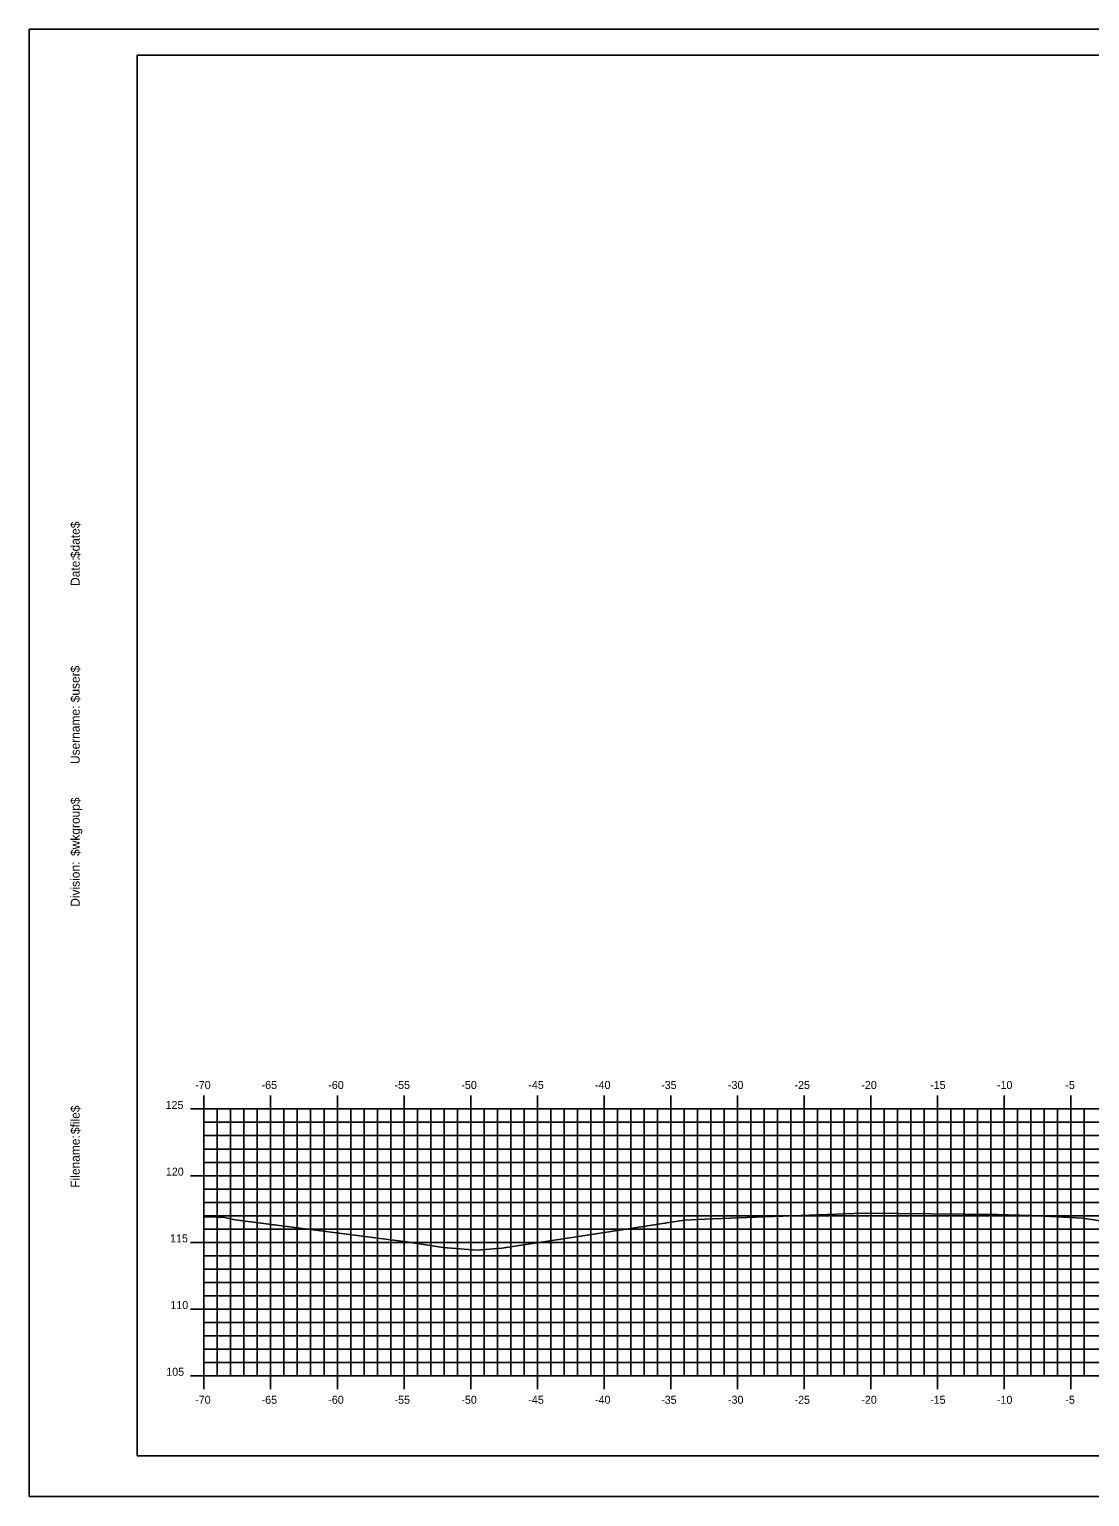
# Model space of a CAD drawing. Extents: x 853956 to 854128, y 365624 to 365734.
# Drawn here: x 853956 to 854035.5, y 365624 to 365734 of the extents above; entities that cross this region are included whole.
import ezdxf

# ---------------------------------------------------------------- set-up
doc = ezdxf.new("R2010")
doc.units = 0
for name, color, linetype in [('BORDER', 7, 'Continuous'), ('H_V ANNOTATION', 7, 'Continuous'), ('M_Roadway_Centerline', 7, 'Continuous'), ('MAJOR', 7, 'Continuous'), ('MINOR', 7, 'Continuous'), ('PLOT BOUNDARY', 7, 'Continuous'), ('S_Roadway_Centerline', 7, 'Continuous')]:
    doc.layers.add(name, color=color, linetype=linetype)

msp = doc.modelspace()

# ---------------------------------------------------------------- linework, layer by layer
at = {"layer": 'BORDER'}
msp.add_lwpolyline([(853964.09, 365627.03), (854124.09, 365627.03), (854124.09, 365732.03), (853964.09, 365732.03)], close=True, dxfattribs=at)
at = {"layer": 'MAJOR'}
for p, q in [((853969.09, 365654.03), (853969.09, 365653.03)), ((853974.09, 365654.03), (853974.09, 365653.03)), ((853979.09, 365654.03), (853979.09, 365653.03)), ((853984.09, 365654.03), (853984.09, 365653.03)), ((853989.09, 365654.03), (853989.09, 365653.03)), ((853994.09, 365654.03), (853994.09, 365653.03)), ((853999.09, 365654.03), (853999.09, 365653.03)), ((854004.09, 365654.03), (854004.09, 365653.03)), ((854009.09, 365654.03), (854009.09, 365653.03)), ((854014.09, 365654.03), (854014.09, 365653.03)), ((854019.09, 365654.03), (854019.09, 365653.03)), ((854024.09, 365654.03), (854024.09, 365653.03)), ((854029.09, 365654.03), (854029.09, 365653.03)), ((854034.09, 365654.03), (854034.09, 365653.03)), ((853968.09, 365653.03), (853969.09, 365653.03)), ((853969.09, 365653.03), (854109.09, 365653.03)), ((853969.09, 365633.03), (853969.09, 365653.03)), ((853969.09, 365633.03), (853969.09, 365653.03)), ((853969.09, 365653.03), (854109.09, 365653.03)), ((853974.09, 365633.03), (853974.09, 365653.03)), ((853979.09, 365633.03), (853979.09, 365653.03)), ((853984.09, 365633.03), (853984.09, 365653.03)), ((853989.09, 365633.03), (853989.09, 365653.03)), ((853994.09, 365633.03), (853994.09, 365653.03)), ((853999.09, 365633.03), (853999.09, 365653.03)), ((854004.09, 365633.03), (854004.09, 365653.03)), ((854009.09, 365633.03), (854009.09, 365653.03)), ((854014.09, 365633.03), (854014.09, 365653.03)), ((854019.09, 365633.03), (854019.09, 365653.03)), ((854024.09, 365633.03), (854024.09, 365653.03)), ((854029.09, 365633.03), (854029.09, 365653.03)), ((854034.09, 365633.03), (854034.09, 365653.03)), ((853968.09, 365648.03), (853969.09, 365648.03)), ((853969.09, 365648.03), (854109.09, 365648.03)), ((853968.09, 365643.03), (853969.09, 365643.03)), ((853969.09, 365643.03), (854109.09, 365643.03)), ((853968.09, 365638.03), (853969.09, 365638.03)), ((853969.09, 365638.03), (854109.09, 365638.03)), ((853968.09, 365633.03), (853969.09, 365633.03)), ((853969.09, 365633.03), (854109.09, 365633.03)), ((853969.09, 365633.03), (854109.09, 365633.03)), ((853969.09, 365632.02), (853969.09, 365633.03)), ((853974.09, 365632.02), (853974.09, 365633.03)), ((853979.09, 365632.02), (853979.09, 365633.03)), ((853984.09, 365632.02), (853984.09, 365633.03)), ((853989.09, 365632.02), (853989.09, 365633.03)), ((853994.09, 365632.02), (853994.09, 365633.03)), ((853999.09, 365632.02), (853999.09, 365633.03)), ((854004.09, 365632.02), (854004.09, 365633.03)), ((854009.09, 365632.02), (854009.09, 365633.03)), ((854014.09, 365632.02), (854014.09, 365633.03)), ((854019.09, 365632.02), (854019.09, 365633.03)), ((854024.09, 365632.02), (854024.09, 365633.03)), ((854029.09, 365632.02), (854029.09, 365633.03)), ((854034.09, 365632.02), (854034.09, 365633.03))]:
    msp.add_line(p, q, dxfattribs=at)
at = {"layer": 'MINOR'}
for p, q in [((853970.09, 365633.03), (853970.09, 365653.03)), ((853971.09, 365633.03), (853971.09, 365653.03)), ((853972.09, 365633.03), (853972.09, 365653.03)), ((853973.09, 365633.03), (853973.09, 365653.03)), ((853975.09, 365633.03), (853975.09, 365653.03)), ((853976.09, 365633.03), (853976.09, 365653.03)), ((853977.09, 365633.03), (853977.09, 365653.03)), ((853978.09, 365633.03), (853978.09, 365653.03)), ((853980.09, 365633.03), (853980.09, 365653.03)), ((853981.09, 365633.03), (853981.09, 365653.03)), ((853982.09, 365633.03), (853982.09, 365653.03)), ((853983.09, 365633.03), (853983.09, 365653.03)), ((853985.09, 365633.03), (853985.09, 365653.03)), ((853986.09, 365633.03), (853986.09, 365653.03)), ((853987.09, 365633.03), (853987.09, 365653.03)), ((853988.09, 365633.03), (853988.09, 365653.03)), ((853990.09, 365633.03), (853990.09, 365653.03)), ((853991.09, 365633.03), (853991.09, 365653.03)), ((853992.09, 365633.03), (853992.09, 365653.03)), ((853993.09, 365633.03), (853993.09, 365653.03)), ((853995.09, 365633.03), (853995.09, 365653.03)), ((853996.09, 365633.03), (853996.09, 365653.03)), ((853997.09, 365633.03), (853997.09, 365653.03)), ((853998.09, 365633.03), (853998.09, 365653.03)), ((854000.09, 365633.03), (854000.09, 365653.03)), ((854001.09, 365633.03), (854001.09, 365653.03)), ((854002.09, 365633.03), (854002.09, 365653.03)), ((854003.09, 365633.03), (854003.09, 365653.03)), ((854005.09, 365633.03), (854005.09, 365653.03)), ((854006.09, 365633.03), (854006.09, 365653.03)), ((854007.09, 365633.03), (854007.09, 365653.03)), ((854008.09, 365633.03), (854008.09, 365653.03)), ((854010.09, 365633.03), (854010.09, 365653.03)), ((854011.09, 365633.03), (854011.09, 365653.03)), ((854012.09, 365633.03), (854012.09, 365653.03)), ((854013.09, 365633.03), (854013.09, 365653.03)), ((854015.09, 365633.03), (854015.09, 365653.03)), ((854016.09, 365633.03), (854016.09, 365653.03)), ((854017.09, 365633.03), (854017.09, 365653.03)), ((854018.09, 365633.03), (854018.09, 365653.03)), ((854020.09, 365633.03), (854020.09, 365653.03)), ((854021.09, 365633.03), (854021.09, 365653.03)), ((854022.09, 365633.03), (854022.09, 365653.03)), ((854023.09, 365633.03), (854023.09, 365653.03)), ((854025.09, 365633.03), (854025.09, 365653.03)), ((854026.09, 365633.03), (854026.09, 365653.03)), ((854027.09, 365633.03), (854027.09, 365653.03)), ((854028.09, 365633.03), (854028.09, 365653.03)), ((854030.09, 365633.03), (854030.09, 365653.03)), ((854031.09, 365633.03), (854031.09, 365653.03)), ((854032.09, 365633.03), (854032.09, 365653.03)), ((854033.09, 365633.03), (854033.09, 365653.03)), ((854035.09, 365633.03), (854035.09, 365653.03)), ((853969.09, 365652.03), (854109.09, 365652.03)), ((853969.09, 365652.03), (853970.09, 365652.03)), ((853969.09, 365651.03), (854109.09, 365651.03)), ((853969.09, 365651.03), (853970.09, 365651.03)), ((853969.09, 365650.03), (854109.09, 365650.03)), ((853969.09, 365650.03), (853970.09, 365650.03)), ((853969.09, 365649.03), (854109.09, 365649.03)), ((853969.09, 365649.03), (853970.09, 365649.03)), ((853969.09, 365647.03), (854109.09, 365647.03)), ((853969.09, 365647.03), (853970.09, 365647.03)), ((853969.09, 365646.03), (854109.09, 365646.03)), ((853969.09, 365646.03), (853970.09, 365646.03)), ((853969.09, 365645.03), (854109.09, 365645.03)), ((853969.09, 365645.03), (853970.09, 365645.03)), ((853969.09, 365644.03), (854109.09, 365644.03)), ((853969.09, 365644.03), (853970.09, 365644.03)), ((853969.09, 365642.03), (854109.09, 365642.03)), ((853969.09, 365642.03), (853970.09, 365642.03)), ((853969.09, 365641.03), (854109.09, 365641.03)), ((853969.09, 365641.03), (853970.09, 365641.03)), ((853969.09, 365640.03), (854109.09, 365640.03)), ((853969.09, 365640.03), (853970.09, 365640.03)), ((853969.09, 365639.03), (854109.09, 365639.03)), ((853969.09, 365639.03), (853970.09, 365639.03)), ((853969.09, 365637.03), (854109.09, 365637.03)), ((853969.09, 365637.03), (853970.09, 365637.03)), ((853969.09, 365636.03), (854109.09, 365636.03)), ((853969.09, 365636.03), (853970.09, 365636.03)), ((853969.09, 365635.03), (854109.09, 365635.03)), ((853969.09, 365635.03), (853970.09, 365635.03)), ((853969.09, 365634.03), (854109.09, 365634.03)), ((853969.09, 365634.03), (853970.09, 365634.03))]:
    msp.add_line(p, q, dxfattribs=at)
at = {"layer": 'PLOT BOUNDARY'}
msp.add_lwpolyline([(853955.99, 365623.97), (854125.99, 365623.97), (854125.99, 365733.97), (853955.99, 365733.97)], close=True, dxfattribs=at)
at = {"layer": 'S_Roadway_Centerline'}
msp.add_lwpolyline([(853969.09, 365644.94), (853970.11, 365644.93), (853970.53, 365644.91), (853971.21, 365644.76), (853971.44, 365644.72), (853984.28, 365643.07), (853987.01, 365642.64), (853989.57, 365642.45), (853991.43, 365642.6), (853998.15, 365643.62), (854005.09, 365644.69), (854006.65, 365644.76), (854009.82, 365644.89), (854017.84, 365645.2), (854018.63, 365645.22), (854028.6, 365645.11), (854031.08, 365645.04), (854034.97, 365644.85), (854037.82, 365644.41)], dxfattribs=at)

# ---------------------------------------------------------------- texts
at = {"layer": 'BORDER'}
for s, p in [('$date$', (853959.77, 365694.33)), ('Date:', (853959.77, 365692.24)), ('$user$', (853959.77, 365683.52)), ('Username:', (853959.77, 365678.89)), ('$wkgroup$', (853959.77, 365672)), ('Division:', (853959.77, 365668.19)), ('$file$', (853959.77, 365651.15)), ('Filename:', (853959.77, 365647.13))]:
    msp.add_text(s, height=0.67, rotation=90, dxfattribs=at).set_placement(p)
at = {"layer": 'H_V ANNOTATION'}
for s, p in [('-70', (853968.43, 365654.53)), ('-65', (853973.41, 365654.53)), ('-60', (853978.41, 365654.53)), ('-55', (853983.38, 365654.53)), ('-50', (853988.39, 365654.53)), ('-45', (853993.41, 365654.53)), ('-40', (853998.41, 365654.53)), ('-35', (854003.37, 365654.53)), ('-30', (854008.38, 365654.53)), ('-25', (854013.37, 365654.53)), ('-20', (854018.38, 365654.53)), ('-15', (854023.54, 365654.53)), ('-10', (854028.55, 365654.53)), ('-5', (854033.68, 365654.53)), ('125', (853966.21, 365653.03)), ('120', (853966.23, 365648.03)), ('115', (853966.55, 365643.03)), ('110', (853966.57, 365638.03)), ('105', (853966.26, 365633.03)), ('-70', (853968.43, 365630.93)), ('-65', (853973.41, 365630.93)), ('-60', (853978.41, 365630.93)), ('-55', (853983.38, 365630.93)), ('-50', (853988.39, 365630.93)), ('-45', (853993.41, 365630.93)), ('-40', (853998.41, 365630.93)), ('-35', (854003.37, 365630.93)), ('-30', (854008.38, 365630.93)), ('-25', (854013.37, 365630.93)), ('-20', (854018.38, 365630.93)), ('-15', (854023.54, 365630.93)), ('-10', (854028.55, 365630.93)), ('-5', (854033.68, 365630.93))]:
    msp.add_text(s, height=0.6, dxfattribs=at).set_placement(p)
at = {"layer": 'M_Roadway_Centerline'}
for s, p in [('C', (854017.83, 365645.2)), ('L', (854017.84, 365645.19))]:
    msp.add_text(s, height=0.0146, dxfattribs=at).set_placement(p)
at = {"layer": 'MAJOR'}
msp.add_text('-', height=0.006, dxfattribs=at).set_placement((853969.08, 365633.03))

doc.saveas('drawing.dxf')
